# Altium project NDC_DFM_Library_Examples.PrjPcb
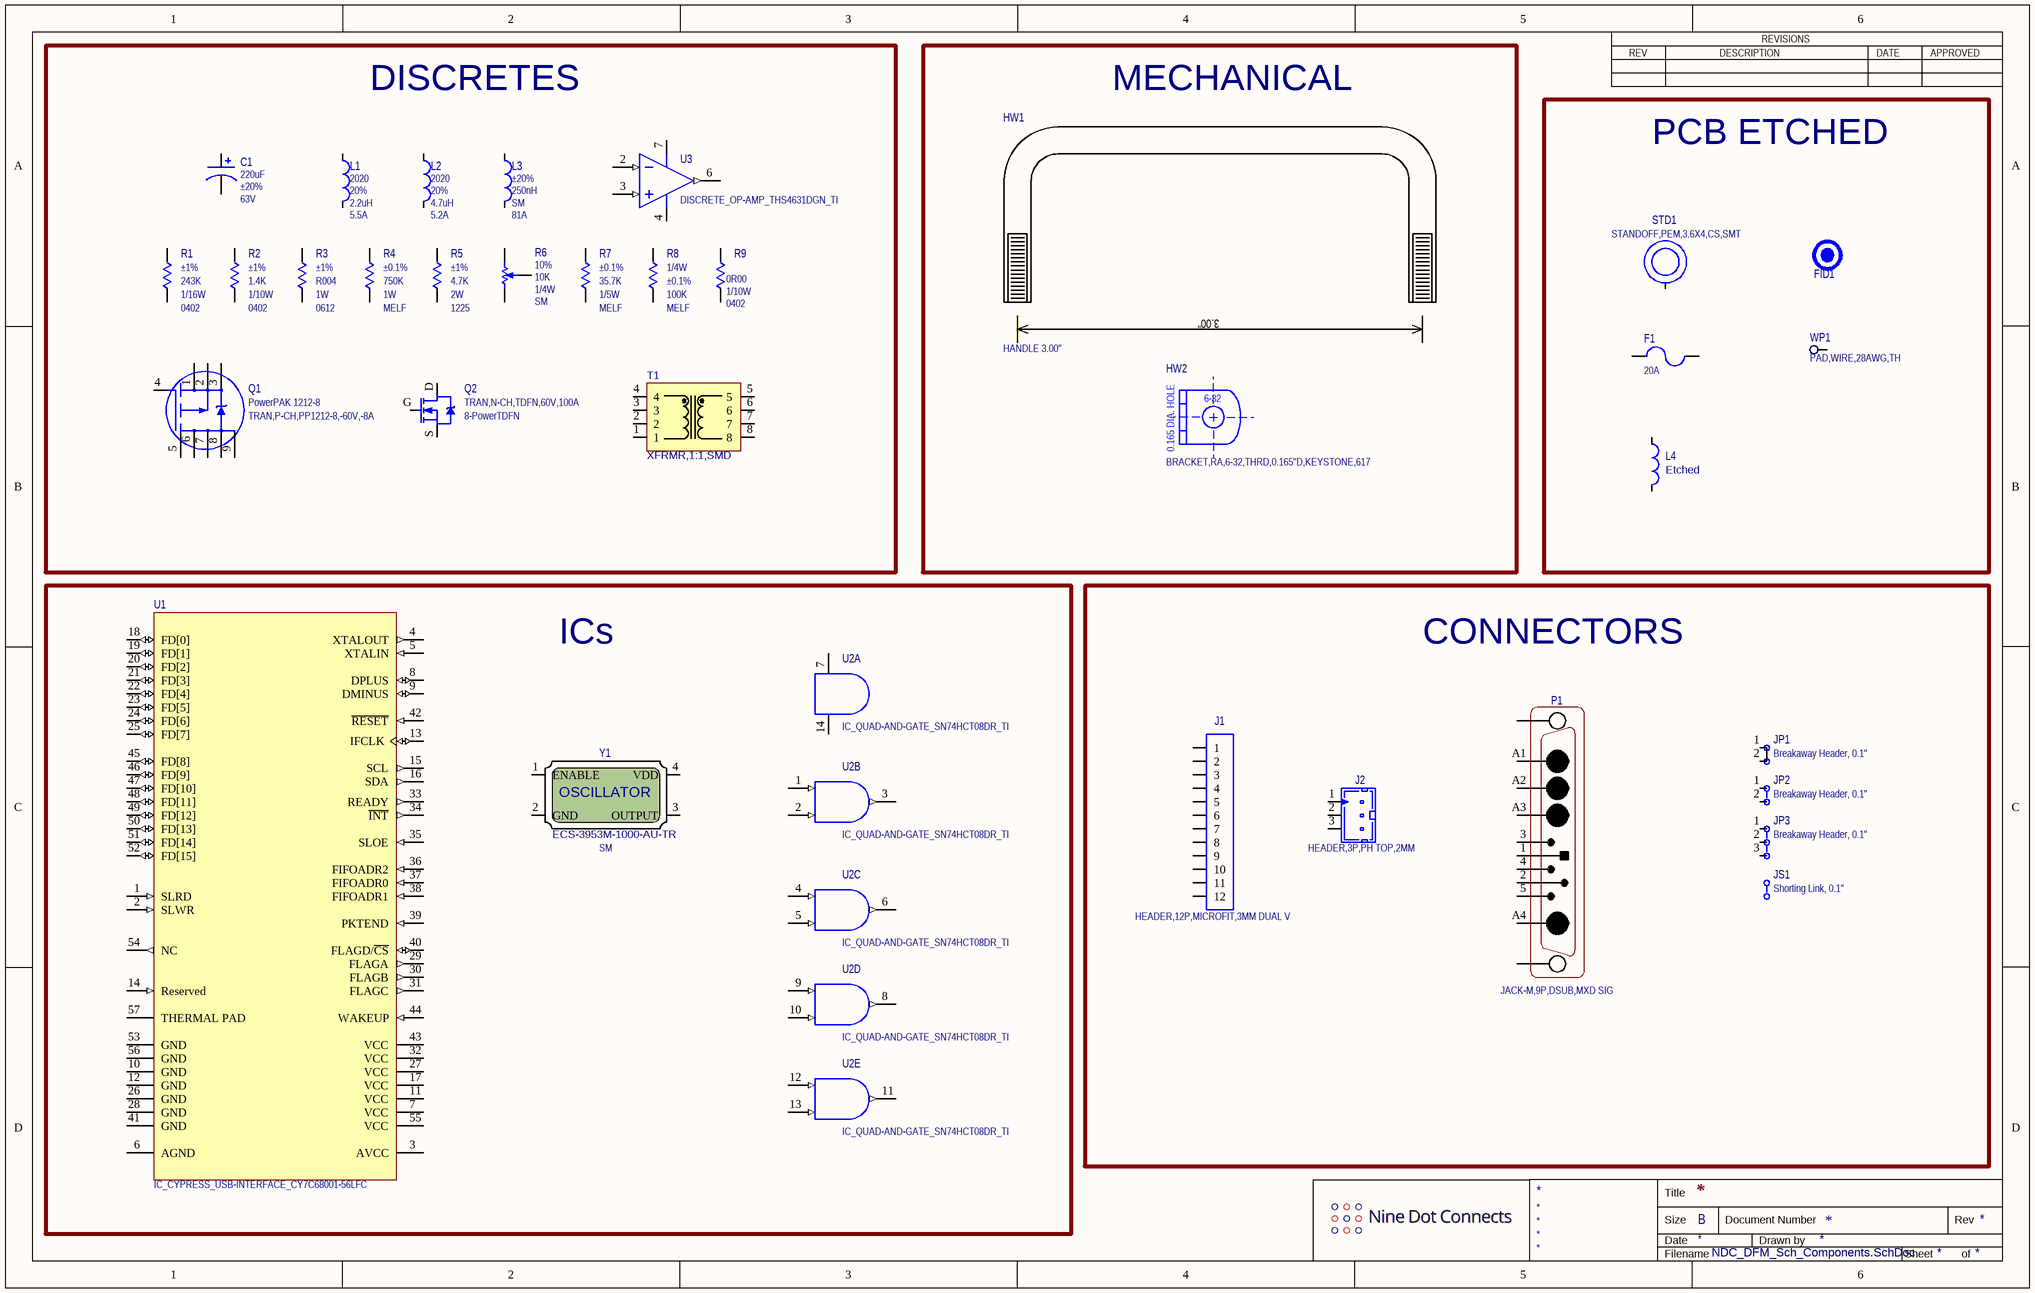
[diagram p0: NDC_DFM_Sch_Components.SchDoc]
2 sheets, 34 parts. Net scope: global (net labels, ports and power ports of the same name join across sheets).
Board file: NDC_DFM_Library_Examples.PcbDoc
Sheets:
  NDC_DFM_Sch_Components.SchDoc
  NDC_DFM_SCH_Top.SchDoc

## Sheet NDC_DFM_Sch_Components.SchDoc
size B

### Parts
C1  value 220uF  Tolerance: ±20%  Voltage Rating: 63V  [Panasonic_CAP_SM_H13]  (hidden comment: CAP,ALUM,227,63V,20%,SMD)
F1  20A  [PCB_FUSE-20A]  (net tie, no BOM)
FID1  FID  [PCB_FID-TARGET-SM]  (value not drawn)  (no BOM)
HW1  HANDLE 3.00"  [KEYSTONE_HANDLE-7173]  (mechanical)
HW2  BRACKET,RA,6-32,THRD,0.165"D,KEYSTONE,617  [KEYSTONE_BRACKET-617]  (mechanical)
J1  HEADER,12P,MICROFIT,3MM DUAL V  [Molex_43045-1212]
J2  HEADER,3P,PH TOP,2MM  [JST_B3B-PH-K-S]
JP1  Breakaway Header, 0.1"  [TE_HDR1X2-CUT-TRACE]
JP2  Breakaway Header, 0.1"  [TE_HDR1X2]
JP3  Breakaway Header, 0.1"  [TE_HDR1X3]
JS1  Shorting Link, 0.1"  [SULLINS_JMPR-SOCKET-1X2]  (mechanical)
L1  value 2.2uH  Package / Case: 2020  Tolerance: 20%  SatCur: 5.5A  [VISHAY_IND-IHLP2020CZ-11]  (hidden comment: IND,2.2uH,2020,5.5A,20%)
L2  value 4.7uH  Package / Case: 2020  Tolerance: 20%  SatCur: 5.2A  [VISHAY_IND-IHLP2020CZ-11]  (hidden comment: IND,4.7uH,202,5.2A,20%)
L3  value 250nH  Tolerance: ±20%  PKG: SM  SatCur: 81A  [VISHAY-IND-WE-HCM]  (hidden comment: IND,250nH,SM,50A,81A ISAT)
L4  Package / Case: Etched  [GENERIC_PLANAR-1:1]  (hidden comment: IND,Etched)  (net tie, no BOM)
P1  JACK-M,9P,DSUB,MXD SIG  [FCT_DB-9W4-M-S-PCB-MOD]
Q1  TRAN,P-CH,PP1212-8,-60V,-8A  PKG: PowerPAK 1212-8  [VISHAY_QFN65P330X330X112-10N]
Q2  TRAN,N-CH,TDFN,60V,100A  Package / Case: 8-PowerTDFN  [INFINEON_TDSON-8]
R1  value 243K  Tolerance: ±1%  Power: 1/16W  PKG: 0402  [STACKPOLE_RESC1005X04N(0402)]  (hidden comment: RES,243K,0402,1%,1/16W)
R2  value 1.4K  TOLERANCE: ±1%  Power: 1/10W  PKG: 0402  [STACKPOLE_RESC1005X04N(0402)]  (hidden comment: RES,1.4K,0402,1%,1/10W)
R3  value R004  Tolerance: ±1%  Power: 1W  PKG: 0612  [VISHAY_RES1632(0612)-RSNS]  (hidden comment: RES-SENSOR,R004,0612,1%,1W)
R4  value 750K  Power: 1W  Tolerance: ±0.1%  PKG: MELF  [VISHAY_MELF-MMB-0207]  (hidden comment: RES,750K,MELF0204,1%,1W)
R5  value 4.7K  Tolerance: ±1%  Power: 2W  PKG: 1225  [VISHAY_RES3263(1225)]  (hidden comment: RES,4.7K,1225WIDE,1%,2W)
R6  value 10K  Tolerance: 10%  Power: 1/4W  PKG: SM  [RPOT_3224W_44W]  (hidden comment: RES-POT,10K,SM,10%,1/4W)
R7  value 35.7K  Tolerance: ±0.1%  Power: 1/5W  PKG: MELF  [VISHAY_MELF-MMU-0102]  (hidden comment: RES,35.7K,MELF010,0.1%,1/5W)
R8  value 100K  Power: 1/4W  Tolerance: ±0.1%  PKG: MELF  [VISHAY_MELF-MMA-0204]  (hidden comment: RES,100K,MELF0204,0.1%,1/4W)
R9  value 0R00  Power: 1/10W  PKG: 0402  [STACKPOLE_RESC1005X04N(0402)]  (hidden comment: RES,0R00,0402,1/10W)
STD1  STANDOFF,PEM,3.6X4,CS,SMT  [PENN_PEM-SMTSO-3.6-4DT]
T1  XFRMR,1:1,SMD  [PPT_PT4812]
U1  IC_CYPRESS_USB-INTERFACE_CY7C68001-56LFC  [CYPRESS_QFN50P800X800-HS-57]
U2  IC_QUAD-AND-GATE_SN74HCT08DR_TI  [TI_SOIC_14]  (parts A,B,C,D,E of 5)
U3  DISCRETE_OP-AMP_THS4631DGN_TI  [TI_DGN8-EP]
WP1  PAD,WIRE,28AWG,TH  [GENERIC_WP28]
Y1  ECS-3953M-1000-AU-TR  PKG: SM  [ECS_3953M-1000-AU-TR]

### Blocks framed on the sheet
DISCRETES: C1 L1-L3 Q1 Q2 R1-R9 T1 U3
MECHANICAL: HW1 HW2
PCB ETCHED: F1 FID1 L4 STD1 WP1
ICs: U1 U2 Y1
CONNECTORS: J1 J2 JP1-JP3 JS1 P1

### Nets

Not connected (* = marked no-connect by the designer): C1 1 2; F1 1 2; J1 1 2 3 4 5 6 7 8 9 10 11 12; J2 1 2 3; JP1 1 2; JP2 1 2; JP3 1 2 3; L1 1 2; L2 1 2; L3 1 2; L4 1 2; P1 1 2 3 4 5 A1 A2 A3 A4 C; Q1 1(S) 2(S) 3(S) 4(G) 5(D) 6(D) 7(D) 8(D) 9(D); Q2 D G S; R1 1 2; R2 1 2; R3 1 2; R4 1 2; R5 1 2; R6 1(CCW) 2(W) 3(CW); R7 1 2; R8 1 2; R9 1 2; STD1 1(MH); T1 1 2 3 4 5 6 7 8; U1 1(SLRD) 2(SLWR) 3(AVCC) 4(XTALOUT) 5(XTALIN) 6(AGND) 7(VCC) 8(DPLUS) 9(DMINUS) 10(GND) 11(VCC) 12(GND) 13(IFCLK) 14(Reserved) 15(SCL) 16(SDA) 17(VCC) 18(FD[0]) 19(FD[1]) 20(FD[2]) 21(FD[3]) 22(FD[4]) 23(FD[5]) 24(FD[6]) 25(FD[7]) 26(GND) 27(VCC) 28(GND) 29(FLAGA) 30(FLAGB) 31(FLAGC) 32(VCC) 33(READY) 34(~{INT}) 35(SLOE) 36(FIFOADR2) 37(FIFOADR0) 38(FIFOADR1) 39(PKTEND) 40(FLAGD/~{CS}) 41(GND) 42(~{RESET}) 43(VCC) 44(WAKEUP) 45(FD[8]) 46(FD[9]) 47(FD[10]) 48(FD[11]) 49(FD[12]) 50(FD[13]) 51(FD[14]) 52(FD[15]) 53(GND) 54(NC) 55(VCC) 56(GND) 57(THERMAL_PAD); U2 1(A) 2(B) 3(Y) 4(A) 5(B) 6(Y) 7(GND) 8(Y) 9(A) 10(B) 11(Y) 12(A) 13(B) 14(VCC); U3 1(NC) 2(IN-) 3(IN+) 4(V-) 6(OUT) 7(V+) 8(NC); WP1 1(WP28); Y1 1(ENABLE) 2(GND) 3(OUTPUT) 4(VDD)

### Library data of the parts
C1 = DISCRETE_CAP_SM_227uF_63V_H13.5_PANASONIC: Manufacturer: Panasonic Electronic Components; Manufacturer Part Number: EEV-FK1J221Q; CompanyPN: 1004222
F1 = PCB_FUSE-20A: PCB FEATURE; CompanyPN: 1004227
FID1 = PCB_FID-TARGET-SM: PCB FEATURE; CompanyPN: 1004226
HW1 = MECH_HANDLE_RACK_3IN_KEYSTONE: HANDLE,ALUM,BLK,3.00",8-32; Manufacturer: Keystone Electronics; Manufacturer Part Number: 7173; CompanyPN: 1004228
HW2 = MECH_BRACKET_RA_KEYSTONE: Manufacturer: Keystone Electronics; Manufacturer Part Number: 617; CompanyPN: 1004221
J1 = CONN_43045-1212_MOLEX: Manufacturer: MOLEX; CompanyPN: 1004237
J2 = CONN_B3B-PH-K-S_JST: Manufacturer: JST Sales America Inc; Manufacturer Part Number: B3B-PH-K-S(LF)(SN); CompanyPN: 1004223; Value: 2.00mm
JP1 = CONN_JUMPER-2PIN-CUT-TRACE_TE: Breakaway Header, 2.54mm (0.1") Pitch; Manufacturer: TE Connectivity / AMP; Manufacturer Part Number: 826646-2; CompanyPN: 1004233
JP2 = CONN_JUMPER-2PIN_TE: Breakaway Header, 2.54mm (0.1") Pitch; Manufacturer: TE Connectivity / AMP; Manufacturer Part Number: 826646-2; CompanyPN: 1004232
JP3 = CONN_JUMPER-3PIN_TE: Breakaway Header, 2.54mm (0.1") Pitch; Manufacturer: TE Connectivity / AMP; Manufacturer Part Number: 826646-2; CompanyPN: 1004234
JS1 = CONN_JUMPER-SHORTING_TE: Shorting Link, 2.54mm (0.1") Pitch; Manufacturer: Sullins Connector Solutions; Manufacturer Part Number: NPN02SXLN-RC; CompanyPN: 1004235
L1 = DISCRETE_IND-SM_2.2uH_5.5A_20%_VISHAY: Manufacturer: Vishay / Dale; Manufacturer Part Number: IHLP2020CZER2R2M11; CompanyPN: 1004229
L2 = DISCRETE_IND-SM_4.7uH_5.2A_20%_VISHAY: Manufacturer: Vishay / Dale; Manufacturer Part Number: IHLP2020CZER4R7M11; CompanyPN: 1004230
L3 = DISCRETE_IND-SM_250NH_50A_VISHAY: Manufacturer: Wurth Electronics Inc; Manufacturer Part Number: 744309025; CompanyPN: 1004231
L4 = PCB_IND-SM: CompanyPN: 1004255; PKG: SM
P1 = CONN_DB-9W4-M-S-PCB_FCT: Manufacturer: FCT ELECTRONICS; Manufacturer Part Number: FM9W4P1-2519; CompanyPN: 1004225
Q1 = DISCRETE_TRAN-SM_P-CH_SI7309DN_PP1212-8_VISHAY: Manufacturer: Vishay; CompanyPN: 1004248
Q2 = DISCRETE_TRAN-SM_N-CH_60V_100A_TDSON-8_INFINEON: Manufacturer: Infineon Technologies; Manufacturer Part Number: BSC028N06NS; CompanyPN: 1004249
R1 = DISCRETE_RES0402_243K_1%_1/16W_STACKPOLE: Manufacturer: Stackpole Electronics Inc; Manufacturer Part Number: RMCF0402FT243K; CompanyPN: 1004240; Voltage Rating: 50V
R2 = DISCRETE_RES0402_1.4K_1%_1/10W_PANASONIC: Manufacturer Part Number: ERJ2RKF1401X; Manufacturer: PANASONIC ELECTRONIC COMPONENTS; CompanyPN: 1004244; Voltage Rating: 50V
R3 = DISCRETE_RES0612_R004_1%_1W_VISHAY: RES,R004,0612,1%,1W; Manufacturer: Vishay / Dale; Manufacturer Part Number: WSK06124L000FEA; CompanyPN: 1004241
R4 = DISCRETE_RES_MELF_0207_750K_1%_1W_VISHAY: Manufacturer: Vishay / Beyschlag; Manufacturer Part Number: MMB02070C7503FB200; CompanyPN: 1004253; Voltage Rating: 350V
R5 = DISCRETE_RES1225_4.7K_1%_2W_1225WIDE_VISHAY: Manufacturer: Vishay / Draloric; Manufacturer Part Number: RCL12254K70FKEG; Voltage Rating: 200V; CompanyPN: 1004242
R6 = DISCRETE_RES-SM-POT_10K_MULTI_1/4W_BiTECH: Manufacturer: BI Technologies / TT electronics; Manufacturer Part Number: 44WR10KLFT7; CompanyPN: 1004245; Voltage Rating: 300V
R7 = DISCRETE_RES_MELF_010_35.7K_0.1%_1/5W_VISHAY: Manufacturer: Vishay / Draloric; Manufacturer Part Number: SMM01020D3572BB300; CompanyPN: 1004252; Voltage Rating: 200V
R8 = DISCRETE_RES_MELF_0204_100K_0.1%_1/4W_VISHAY: Manufacturer: Vishay / Draloric; Manufacturer Part Number: SMM02040E1003BB300; CompanyPN: 1004251; Voltage Rating: 200V
R9 = DISCRETE_RES0402_0R00_PANASONIC: Manufacturer Part Number: ERJ-2GE0R00X; Manufacturer: PANASONIC ELECTRONIC COMPONENTS; CompanyPN: 1004243; Voltage Rating: 50V
STD1 = MECH_STANDOFF_PEM_3.6X4_CS_SMT_PENN: Manufacturer Part Number: SMTSO-3.6-4DT; Manufacturer: Penn Engineering; CompanyPN: 1004246; Value: SMTSO-3.6-4DT
T1 = DISCRETE_XFRMR_PT4812_PPT: Manufacturer: PPT Magnetics (China); Manufacturer Part Number: PT-4812; CompanyPN: 1004239
U1 = IC_CYPRESS_USB-INTERFACE_CY7C68001-56LFC: CY7C68001-56LFC, EZ-USB SX2 High-Speed USB Interface; Manufacturer: Cypress Semiconductor; CompanyPN: 1004224
U2 = IC_QUAD-AND-GATE_SN74HCT08DR_TI: LogicGate_AND; Manufacturer: Texas Instruments; Manufacturer Part Number: SN74AHCT08DR; CompanyPN: 1004254
U3 = DISCRETE_OP-AMP_THS4631DGN_TI: Operational Amplifier; Manufacturer: Texas Instruments; CompanyPN: 1004247
WP1 = PCB_WIRE_PAD_28AWG: Manufacturer: PCB FEATURE; CompanyPN: 1004250
Y1 = IC_ECS_OSC-100.000-MHZ-3.3V-SMD: OSC 100.000 MHZ 3.3V SMD; Manufacturer: ECS Inc; CompanyPN: 1004238

## Sheet NDC_DFM_SCH_Top.SchDoc
size B
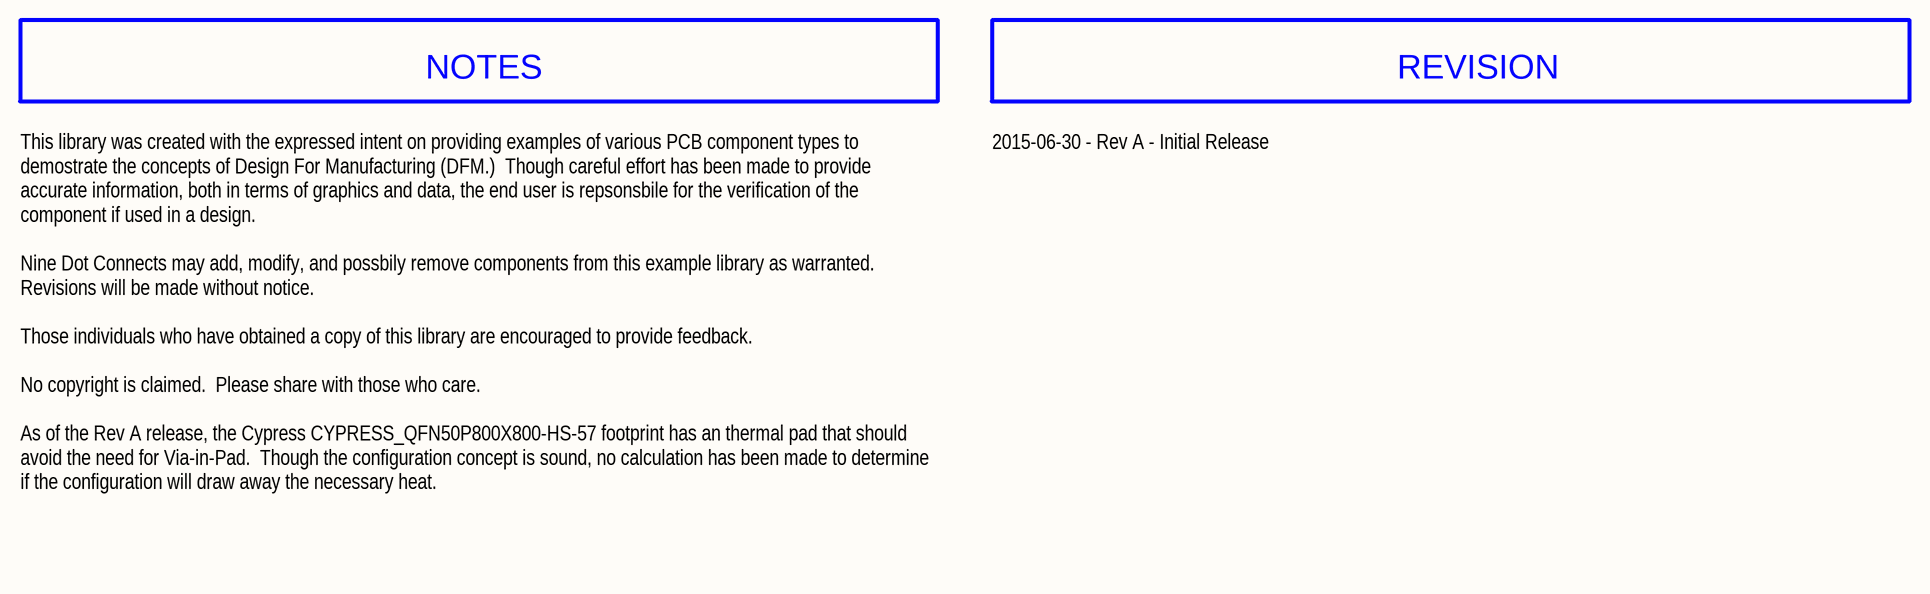
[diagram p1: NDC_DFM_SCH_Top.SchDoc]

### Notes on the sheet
- NOTES
- REVISION
- 2015-06-30 - Rev A - Initial Release
- This library was created with the expressed intent on providing examples of various PCB component types to demostrate the concepts of Design For Manufacturing (DFM.)  Though careful effort has been made to provide accurate information, both in terms of graphics and data, the end user is repsonsbile for the verification of the component if used in a design.
  Nine Dot Connects may add, modify, and possbily remove components from this example library as warranted.  Revisions will be made without notice.
  Those individuals who have obtained a copy of this library are encouraged to provide feedback.
  No copyright is claimed.  Please share with those who care.
  As of the Rev A release, the Cypress CYPRESS_QFN50P800X800-HS-57 footprint has an thermal pad that should avoid the need for Via-in-Pad.  Though the configuration concept is sound, no calculation has been made to determine if the configuration will draw away the necessary heat.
